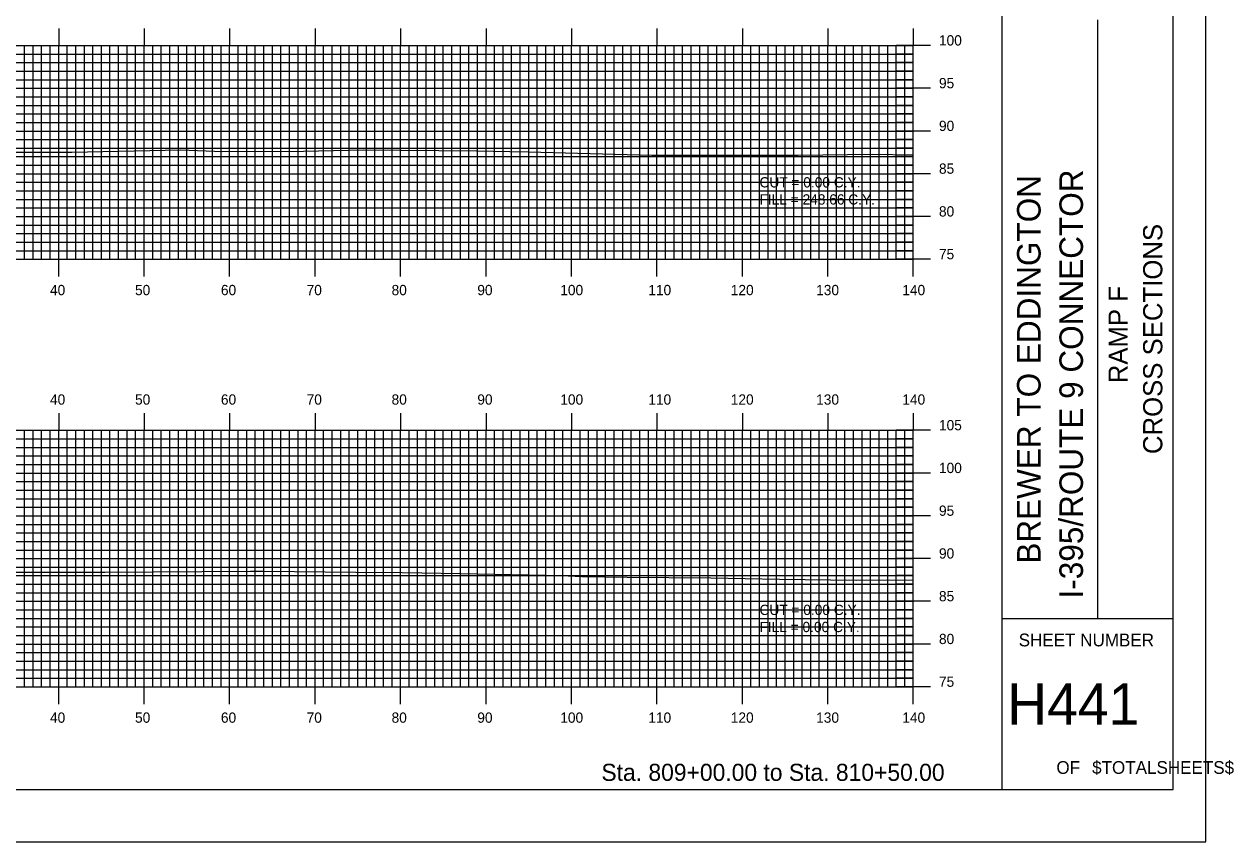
# Model space of a CAD drawing. Extents: x 1666 to 2009, y -1658 to -1438.
# Drawn here: x 1867.6 to 2009.2, y -1657.7 to -1562.1 of the extents above; entities that cross this region are included whole.
import ezdxf

# ---------------------------------------------------------------- set-up
doc = ezdxf.new("R2010")
doc.units = 0
for name, color, linetype in [('BORDER', 7, 'Continuous'), ('D_Text_Standard', 7, 'Continuous'), ('H_V ANNOTATION', 7, 'Continuous'), ('MAJOR', 7, 'Continuous'), ('MINOR', 7, 'Continuous'), ('PLOT BOUNDARY', 7, 'Continuous'), ('S_Roadway_Centerline', 7, 'Continuous')]:
    doc.layers.add(name, color=color, linetype=linetype)

msp = doc.modelspace()

# ---------------------------------------------------------------- linework, layer by layer
at = {"layer": 'BORDER'}
for p, q in [((1982.07, -1651.6), (1982.07, -1441.6)), ((1993.26, -1631.6), (1993.26, -1561.6)), ((1982.07, -1631.6), (2002.07, -1631.6))]:
    msp.add_line(p, q, dxfattribs=at)
msp.add_lwpolyline([(1682.07, -1651.6), (2002.07, -1651.6), (2002.07, -1441.6), (1682.07, -1441.6)], close=True, dxfattribs=at)
at = {"layer": 'MAJOR'}
for p, q in [((1871.67, -1562.6), (1871.67, -1564.6)), ((1881.67, -1562.6), (1881.67, -1564.6)), ((1891.67, -1562.6), (1891.67, -1564.6)), ((1901.67, -1562.6), (1901.67, -1564.6)), ((1911.67, -1562.6), (1911.67, -1564.6)), ((1921.67, -1562.6), (1921.67, -1564.6)), ((1931.67, -1562.6), (1931.67, -1564.6)), ((1941.67, -1562.6), (1941.67, -1564.6)), ((1951.67, -1562.6), (1951.67, -1564.6)), ((1961.67, -1562.6), (1961.67, -1564.6)), ((1971.67, -1562.6), (1971.67, -1564.6)), ((1691.67, -1564.6), (1971.67, -1564.6)), ((1691.67, -1564.6), (1971.67, -1564.6)), ((1871.67, -1589.6), (1871.67, -1564.6)), ((1881.67, -1589.6), (1881.67, -1564.6)), ((1891.67, -1589.6), (1891.67, -1564.6)), ((1901.67, -1589.6), (1901.67, -1564.6)), ((1911.67, -1589.6), (1911.67, -1564.6)), ((1921.67, -1589.6), (1921.67, -1564.6)), ((1931.67, -1589.6), (1931.67, -1564.6)), ((1941.67, -1589.6), (1941.67, -1564.6)), ((1951.67, -1589.6), (1951.67, -1564.6)), ((1961.67, -1589.6), (1961.67, -1564.6)), ((1973.68, -1564.6), (1969.67, -1564.6)), ((1971.67, -1589.6), (1971.67, -1564.6)), ((1971.67, -1589.6), (1971.67, -1564.6)), ((1691.67, -1569.6), (1971.67, -1569.6)), ((1973.68, -1569.6), (1969.67, -1569.6)), ((1691.67, -1574.6), (1971.67, -1574.6)), ((1973.68, -1574.6), (1969.67, -1574.6)), ((1691.67, -1579.6), (1971.67, -1579.6)), ((1973.68, -1579.6), (1969.67, -1579.6)), ((1691.67, -1584.6), (1971.67, -1584.6)), ((1973.68, -1584.6), (1969.67, -1584.6)), ((1691.67, -1589.6), (1971.67, -1589.6)), ((1691.67, -1589.6), (1971.67, -1589.6)), ((1871.67, -1591.61), (1871.67, -1589.6)), ((1881.67, -1591.61), (1881.67, -1589.6)), ((1891.67, -1591.61), (1891.67, -1589.6)), ((1901.67, -1591.61), (1901.67, -1589.6)), ((1911.67, -1591.61), (1911.67, -1589.6)), ((1921.67, -1591.61), (1921.67, -1589.6)), ((1931.67, -1591.61), (1931.67, -1589.6)), ((1941.67, -1591.61), (1941.67, -1589.6)), ((1951.67, -1591.61), (1951.67, -1589.6)), ((1961.67, -1591.61), (1961.67, -1589.6)), ((1973.68, -1589.6), (1969.67, -1589.6)), ((1971.67, -1591.61), (1971.67, -1589.6)), ((1871.67, -1607.6), (1871.67, -1609.6)), ((1881.67, -1607.6), (1881.67, -1609.6)), ((1891.67, -1607.6), (1891.67, -1609.6)), ((1901.67, -1607.6), (1901.67, -1609.6)), ((1911.67, -1607.6), (1911.67, -1609.6)), ((1921.67, -1607.6), (1921.67, -1609.6)), ((1931.67, -1607.6), (1931.67, -1609.6)), ((1941.67, -1607.6), (1941.67, -1609.6)), ((1951.67, -1607.6), (1951.67, -1609.6)), ((1961.67, -1607.6), (1961.67, -1609.6)), ((1971.67, -1607.6), (1971.67, -1609.6)), ((1691.67, -1609.6), (1971.67, -1609.6)), ((1691.67, -1609.6), (1971.67, -1609.6)), ((1871.67, -1639.6), (1871.67, -1609.6)), ((1881.67, -1639.6), (1881.67, -1609.6)), ((1891.67, -1639.6), (1891.67, -1609.6)), ((1901.67, -1639.6), (1901.67, -1609.6)), ((1911.67, -1639.6), (1911.67, -1609.6)), ((1921.67, -1639.6), (1921.67, -1609.6)), ((1931.67, -1639.6), (1931.67, -1609.6)), ((1941.67, -1639.6), (1941.67, -1609.6)), ((1951.67, -1639.6), (1951.67, -1609.6)), ((1961.67, -1639.6), (1961.67, -1609.6)), ((1973.68, -1609.6), (1969.67, -1609.6)), ((1971.67, -1639.6), (1971.67, -1609.6)), ((1971.67, -1639.6), (1971.67, -1609.6)), ((1691.67, -1614.6), (1971.67, -1614.6)), ((1973.68, -1614.6), (1969.67, -1614.6)), ((1691.67, -1619.6), (1971.67, -1619.6)), ((1973.68, -1619.6), (1969.67, -1619.6)), ((1691.67, -1624.6), (1971.67, -1624.6)), ((1973.68, -1624.6), (1969.67, -1624.6)), ((1691.67, -1629.6), (1971.67, -1629.6)), ((1973.68, -1629.6), (1969.67, -1629.6)), ((1691.67, -1634.6), (1971.67, -1634.6)), ((1973.68, -1634.6), (1969.67, -1634.6)), ((1691.67, -1639.6), (1971.67, -1639.6)), ((1691.67, -1639.6), (1971.67, -1639.6)), ((1871.67, -1641.61), (1871.67, -1639.6)), ((1881.67, -1641.61), (1881.67, -1639.6)), ((1891.67, -1641.61), (1891.67, -1639.6)), ((1901.67, -1641.61), (1901.67, -1639.6)), ((1911.67, -1641.61), (1911.67, -1639.6)), ((1921.67, -1641.61), (1921.67, -1639.6)), ((1931.67, -1641.61), (1931.67, -1639.6)), ((1941.67, -1641.61), (1941.67, -1639.6)), ((1951.67, -1641.61), (1951.67, -1639.6)), ((1961.67, -1641.61), (1961.67, -1639.6)), ((1973.68, -1639.6), (1969.67, -1639.6)), ((1971.67, -1641.61), (1971.67, -1639.6))]:
    msp.add_line(p, q, dxfattribs=at)
at = {"layer": 'MINOR'}
for p, q in [((1867.67, -1589.6), (1867.67, -1564.6)), ((1868.67, -1589.6), (1868.67, -1564.6)), ((1869.67, -1589.6), (1869.67, -1564.6)), ((1870.67, -1589.6), (1870.67, -1564.6)), ((1872.67, -1589.6), (1872.67, -1564.6)), ((1873.67, -1589.6), (1873.67, -1564.6)), ((1874.67, -1589.6), (1874.67, -1564.6)), ((1875.67, -1589.6), (1875.67, -1564.6)), ((1876.67, -1589.6), (1876.67, -1564.6)), ((1877.67, -1589.6), (1877.67, -1564.6)), ((1878.67, -1589.6), (1878.67, -1564.6)), ((1879.67, -1589.6), (1879.67, -1564.6)), ((1880.67, -1589.6), (1880.67, -1564.6)), ((1882.67, -1589.6), (1882.67, -1564.6)), ((1883.67, -1589.6), (1883.67, -1564.6)), ((1884.67, -1589.6), (1884.67, -1564.6)), ((1885.67, -1589.6), (1885.67, -1564.6)), ((1886.67, -1589.6), (1886.67, -1564.6)), ((1887.67, -1589.6), (1887.67, -1564.6)), ((1888.67, -1589.6), (1888.67, -1564.6)), ((1889.67, -1589.6), (1889.67, -1564.6)), ((1890.67, -1589.6), (1890.67, -1564.6)), ((1892.67, -1589.6), (1892.67, -1564.6)), ((1893.67, -1589.6), (1893.67, -1564.6)), ((1894.67, -1589.6), (1894.67, -1564.6)), ((1895.67, -1589.6), (1895.67, -1564.6)), ((1896.67, -1589.6), (1896.67, -1564.6)), ((1897.67, -1589.6), (1897.67, -1564.6)), ((1898.67, -1589.6), (1898.67, -1564.6)), ((1899.67, -1589.6), (1899.67, -1564.6)), ((1900.67, -1589.6), (1900.67, -1564.6)), ((1902.67, -1589.6), (1902.67, -1564.6)), ((1903.67, -1589.6), (1903.67, -1564.6)), ((1904.67, -1589.6), (1904.67, -1564.6)), ((1905.67, -1589.6), (1905.67, -1564.6)), ((1906.67, -1589.6), (1906.67, -1564.6)), ((1907.67, -1589.6), (1907.67, -1564.6)), ((1908.67, -1589.6), (1908.67, -1564.6)), ((1909.67, -1589.6), (1909.67, -1564.6)), ((1910.67, -1589.6), (1910.67, -1564.6)), ((1912.67, -1589.6), (1912.67, -1564.6)), ((1913.67, -1589.6), (1913.67, -1564.6)), ((1914.67, -1589.6), (1914.67, -1564.6)), ((1915.67, -1589.6), (1915.67, -1564.6)), ((1916.67, -1589.6), (1916.67, -1564.6)), ((1917.67, -1589.6), (1917.67, -1564.6)), ((1918.67, -1589.6), (1918.67, -1564.6)), ((1919.67, -1589.6), (1919.67, -1564.6)), ((1920.67, -1589.6), (1920.67, -1564.6)), ((1922.67, -1589.6), (1922.67, -1564.6)), ((1923.67, -1589.6), (1923.67, -1564.6)), ((1924.67, -1589.6), (1924.67, -1564.6)), ((1925.67, -1589.6), (1925.67, -1564.6)), ((1926.67, -1589.6), (1926.67, -1564.6)), ((1927.67, -1589.6), (1927.67, -1564.6)), ((1928.67, -1589.6), (1928.67, -1564.6)), ((1929.67, -1589.6), (1929.67, -1564.6)), ((1930.67, -1589.6), (1930.67, -1564.6)), ((1932.67, -1589.6), (1932.67, -1564.6)), ((1933.67, -1589.6), (1933.67, -1564.6)), ((1934.67, -1589.6), (1934.67, -1564.6)), ((1935.67, -1589.6), (1935.67, -1564.6)), ((1936.67, -1589.6), (1936.67, -1564.6)), ((1937.67, -1589.6), (1937.67, -1564.6)), ((1938.67, -1589.6), (1938.67, -1564.6)), ((1939.67, -1589.6), (1939.67, -1564.6)), ((1940.67, -1589.6), (1940.67, -1564.6)), ((1942.67, -1589.6), (1942.67, -1564.6)), ((1943.67, -1589.6), (1943.67, -1564.6)), ((1944.67, -1589.6), (1944.67, -1564.6)), ((1945.67, -1589.6), (1945.67, -1564.6)), ((1946.67, -1589.6), (1946.67, -1564.6)), ((1947.67, -1589.6), (1947.67, -1564.6)), ((1948.67, -1589.6), (1948.67, -1564.6)), ((1949.67, -1589.6), (1949.67, -1564.6)), ((1950.67, -1589.6), (1950.67, -1564.6)), ((1952.67, -1589.6), (1952.67, -1564.6)), ((1953.67, -1589.6), (1953.67, -1564.6)), ((1954.67, -1589.6), (1954.67, -1564.6)), ((1955.67, -1589.6), (1955.67, -1564.6)), ((1956.67, -1589.6), (1956.67, -1564.6)), ((1957.67, -1589.6), (1957.67, -1564.6)), ((1958.67, -1589.6), (1958.67, -1564.6)), ((1959.67, -1589.6), (1959.67, -1564.6)), ((1960.67, -1589.6), (1960.67, -1564.6)), ((1962.67, -1589.6), (1962.67, -1564.6)), ((1963.67, -1589.6), (1963.67, -1564.6)), ((1964.67, -1589.6), (1964.67, -1564.6)), ((1965.67, -1589.6), (1965.67, -1564.6)), ((1966.67, -1589.6), (1966.67, -1564.6)), ((1967.67, -1589.6), (1967.67, -1564.6)), ((1968.67, -1589.6), (1968.67, -1564.6)), ((1969.67, -1589.6), (1969.67, -1564.6)), ((1970.67, -1589.6), (1970.67, -1564.6)), ((1691.67, -1565.6), (1971.67, -1565.6)), ((1691.67, -1566.6), (1971.67, -1566.6)), ((1971.67, -1565.6), (1969.67, -1565.6)), ((1971.67, -1566.6), (1969.67, -1566.6)), ((1691.67, -1567.6), (1971.67, -1567.6)), ((1971.67, -1567.6), (1969.67, -1567.6)), ((1691.67, -1568.6), (1971.67, -1568.6)), ((1971.67, -1568.6), (1969.67, -1568.6)), ((1691.67, -1570.6), (1971.67, -1570.6)), ((1971.67, -1570.6), (1969.67, -1570.6)), ((1691.67, -1571.6), (1971.67, -1571.6)), ((1971.67, -1571.6), (1969.67, -1571.6)), ((1691.67, -1572.6), (1971.67, -1572.6)), ((1691.67, -1573.6), (1971.67, -1573.6)), ((1971.67, -1572.6), (1969.67, -1572.6)), ((1971.67, -1573.6), (1969.67, -1573.6)), ((1691.67, -1575.6), (1971.67, -1575.6)), ((1691.67, -1576.6), (1971.67, -1576.6)), ((1971.67, -1575.6), (1969.67, -1575.6)), ((1971.67, -1576.6), (1969.67, -1576.6)), ((1691.67, -1577.6), (1971.67, -1577.6)), ((1971.67, -1577.6), (1969.67, -1577.6)), ((1691.67, -1578.6), (1971.67, -1578.6)), ((1971.67, -1578.6), (1969.67, -1578.6)), ((1691.67, -1580.6), (1971.67, -1580.6)), ((1971.67, -1580.6), (1969.67, -1580.6)), ((1691.67, -1581.6), (1971.67, -1581.6)), ((1971.67, -1581.6), (1969.67, -1581.6)), ((1691.67, -1582.6), (1971.67, -1582.6)), ((1691.67, -1583.6), (1971.67, -1583.6)), ((1971.67, -1582.6), (1969.67, -1582.6)), ((1971.67, -1583.6), (1969.67, -1583.6)), ((1691.67, -1585.6), (1971.67, -1585.6)), ((1691.67, -1586.6), (1971.67, -1586.6)), ((1971.67, -1585.6), (1969.67, -1585.6)), ((1971.67, -1586.6), (1969.67, -1586.6)), ((1691.67, -1587.6), (1971.67, -1587.6)), ((1971.67, -1587.6), (1969.67, -1587.6)), ((1691.67, -1588.6), (1971.67, -1588.6)), ((1971.67, -1588.6), (1969.67, -1588.6)), ((1691.67, -1610.6), (1971.67, -1610.6)), ((1867.67, -1639.6), (1867.67, -1609.6)), ((1868.67, -1639.6), (1868.67, -1609.6)), ((1869.67, -1639.6), (1869.67, -1609.6)), ((1870.67, -1639.6), (1870.67, -1609.6)), ((1872.67, -1639.6), (1872.67, -1609.6)), ((1873.67, -1639.6), (1873.67, -1609.6)), ((1874.67, -1639.6), (1874.67, -1609.6)), ((1875.67, -1639.6), (1875.67, -1609.6)), ((1876.67, -1639.6), (1876.67, -1609.6)), ((1877.67, -1639.6), (1877.67, -1609.6)), ((1878.67, -1639.6), (1878.67, -1609.6)), ((1879.67, -1639.6), (1879.67, -1609.6)), ((1880.67, -1639.6), (1880.67, -1609.6)), ((1882.67, -1639.6), (1882.67, -1609.6)), ((1883.67, -1639.6), (1883.67, -1609.6)), ((1884.67, -1639.6), (1884.67, -1609.6)), ((1885.67, -1639.6), (1885.67, -1609.6)), ((1886.67, -1639.6), (1886.67, -1609.6)), ((1887.67, -1639.6), (1887.67, -1609.6)), ((1888.67, -1639.6), (1888.67, -1609.6)), ((1889.67, -1639.6), (1889.67, -1609.6)), ((1890.67, -1639.6), (1890.67, -1609.6)), ((1892.67, -1639.6), (1892.67, -1609.6)), ((1893.67, -1639.6), (1893.67, -1609.6)), ((1894.67, -1639.6), (1894.67, -1609.6)), ((1895.67, -1639.6), (1895.67, -1609.6)), ((1896.67, -1639.6), (1896.67, -1609.6)), ((1897.67, -1639.6), (1897.67, -1609.6)), ((1898.67, -1639.6), (1898.67, -1609.6)), ((1899.67, -1639.6), (1899.67, -1609.6)), ((1900.67, -1639.6), (1900.67, -1609.6)), ((1902.67, -1639.6), (1902.67, -1609.6)), ((1903.67, -1639.6), (1903.67, -1609.6)), ((1904.67, -1639.6), (1904.67, -1609.6)), ((1905.67, -1639.6), (1905.67, -1609.6)), ((1906.67, -1639.6), (1906.67, -1609.6)), ((1907.67, -1639.6), (1907.67, -1609.6)), ((1908.67, -1639.6), (1908.67, -1609.6)), ((1909.67, -1639.6), (1909.67, -1609.6)), ((1910.67, -1639.6), (1910.67, -1609.6)), ((1912.67, -1639.6), (1912.67, -1609.6)), ((1913.67, -1639.6), (1913.67, -1609.6)), ((1914.67, -1639.6), (1914.67, -1609.6)), ((1915.67, -1639.6), (1915.67, -1609.6)), ((1916.67, -1639.6), (1916.67, -1609.6)), ((1917.67, -1639.6), (1917.67, -1609.6)), ((1918.67, -1639.6), (1918.67, -1609.6)), ((1919.67, -1639.6), (1919.67, -1609.6)), ((1920.67, -1639.6), (1920.67, -1609.6)), ((1922.67, -1639.6), (1922.67, -1609.6)), ((1923.67, -1639.6), (1923.67, -1609.6)), ((1924.67, -1639.6), (1924.67, -1609.6)), ((1925.67, -1639.6), (1925.67, -1609.6)), ((1926.67, -1639.6), (1926.67, -1609.6)), ((1927.67, -1639.6), (1927.67, -1609.6)), ((1928.67, -1639.6), (1928.67, -1609.6)), ((1929.67, -1639.6), (1929.67, -1609.6)), ((1930.67, -1639.6), (1930.67, -1609.6)), ((1932.67, -1639.6), (1932.67, -1609.6)), ((1933.67, -1639.6), (1933.67, -1609.6)), ((1934.67, -1639.6), (1934.67, -1609.6)), ((1935.67, -1639.6), (1935.67, -1609.6)), ((1936.67, -1639.6), (1936.67, -1609.6)), ((1937.67, -1639.6), (1937.67, -1609.6)), ((1938.67, -1639.6), (1938.67, -1609.6)), ((1939.67, -1639.6), (1939.67, -1609.6)), ((1940.67, -1639.6), (1940.67, -1609.6)), ((1942.67, -1639.6), (1942.67, -1609.6)), ((1943.67, -1639.6), (1943.67, -1609.6)), ((1944.67, -1639.6), (1944.67, -1609.6)), ((1945.67, -1639.6), (1945.67, -1609.6)), ((1946.67, -1639.6), (1946.67, -1609.6)), ((1947.67, -1639.6), (1947.67, -1609.6)), ((1948.67, -1639.6), (1948.67, -1609.6)), ((1949.67, -1639.6), (1949.67, -1609.6)), ((1950.67, -1639.6), (1950.67, -1609.6)), ((1952.67, -1639.6), (1952.67, -1609.6)), ((1953.67, -1639.6), (1953.67, -1609.6)), ((1954.67, -1639.6), (1954.67, -1609.6)), ((1955.67, -1639.6), (1955.67, -1609.6)), ((1956.67, -1639.6), (1956.67, -1609.6)), ((1957.67, -1639.6), (1957.67, -1609.6)), ((1958.67, -1639.6), (1958.67, -1609.6)), ((1959.67, -1639.6), (1959.67, -1609.6)), ((1960.67, -1639.6), (1960.67, -1609.6)), ((1962.67, -1639.6), (1962.67, -1609.6)), ((1963.67, -1639.6), (1963.67, -1609.6)), ((1964.67, -1639.6), (1964.67, -1609.6)), ((1965.67, -1639.6), (1965.67, -1609.6)), ((1966.67, -1639.6), (1966.67, -1609.6)), ((1967.67, -1639.6), (1967.67, -1609.6)), ((1968.67, -1639.6), (1968.67, -1609.6)), ((1969.67, -1639.6), (1969.67, -1609.6)), ((1971.67, -1610.6), (1969.67, -1610.6)), ((1970.67, -1639.6), (1970.67, -1609.6)), ((1691.67, -1611.6), (1971.67, -1611.6)), ((1971.67, -1611.6), (1969.67, -1611.6)), ((1691.67, -1612.6), (1971.67, -1612.6)), ((1971.67, -1612.6), (1969.67, -1612.6)), ((1691.67, -1613.6), (1971.67, -1613.6)), ((1971.67, -1613.6), (1969.67, -1613.6)), ((1691.67, -1615.6), (1971.67, -1615.6)), ((1971.67, -1615.6), (1969.67, -1615.6)), ((1691.67, -1616.6), (1971.67, -1616.6)), ((1691.67, -1617.6), (1971.67, -1617.6)), ((1971.67, -1616.6), (1969.67, -1616.6)), ((1971.67, -1617.6), (1969.67, -1617.6)), ((1691.67, -1618.6), (1971.67, -1618.6)), ((1971.67, -1618.6), (1969.67, -1618.6)), ((1691.67, -1620.6), (1971.67, -1620.6)), ((1971.67, -1620.6), (1969.67, -1620.6)), ((1691.67, -1621.6), (1971.67, -1621.6)), ((1971.67, -1621.6), (1969.67, -1621.6)), ((1691.67, -1622.6), (1971.67, -1622.6)), ((1971.67, -1622.6), (1969.67, -1622.6)), ((1691.67, -1623.6), (1971.67, -1623.6)), ((1971.67, -1623.6), (1969.67, -1623.6)), ((1691.67, -1625.6), (1971.67, -1625.6)), ((1971.67, -1625.6), (1969.67, -1625.6)), ((1691.67, -1626.6), (1971.67, -1626.6)), ((1691.67, -1627.6), (1971.67, -1627.6)), ((1971.67, -1626.6), (1969.67, -1626.6)), ((1971.67, -1627.6), (1969.67, -1627.6)), ((1691.67, -1628.6), (1971.67, -1628.6)), ((1971.67, -1628.6), (1969.67, -1628.6)), ((1691.67, -1630.6), (1971.67, -1630.6)), ((1691.67, -1631.6), (1971.67, -1631.6)), ((1971.67, -1630.6), (1969.67, -1630.6)), ((1971.67, -1631.6), (1969.67, -1631.6)), ((1691.67, -1632.6), (1971.67, -1632.6)), ((1971.67, -1632.6), (1969.67, -1632.6)), ((1691.67, -1633.6), (1971.67, -1633.6)), ((1971.67, -1633.6), (1969.67, -1633.6)), ((1691.67, -1635.6), (1971.67, -1635.6)), ((1971.67, -1635.6), (1969.67, -1635.6)), ((1691.67, -1636.6), (1971.67, -1636.6)), ((1971.67, -1636.6), (1969.67, -1636.6)), ((1691.67, -1637.6), (1971.67, -1637.6)), ((1691.67, -1638.6), (1971.67, -1638.6)), ((1971.67, -1637.6), (1969.67, -1637.6)), ((1971.67, -1638.6), (1969.67, -1638.6))]:
    msp.add_line(p, q, dxfattribs=at)
at = {"layer": 'PLOT BOUNDARY'}
msp.add_lwpolyline([(1665.89, -1657.72), (2005.89, -1657.72), (2005.89, -1437.72), (1665.89, -1437.72)], close=True, dxfattribs=at)
at = {"layer": 'S_Roadway_Centerline'}
for points in [[(1865.74, -1577.06), (1871.37, -1577.09), (1873.2, -1577.06), (1885.96, -1576.81), (1890.88, -1577.01), (1900.32, -1576.97), (1907.32, -1576.82), (1920.55, -1576.91), (1924.47, -1577.01), (1926.64, -1577.05), (1941.08, -1577.41), (1941.7, -1577.42), (1941.81, -1577.42), (1941.98, -1577.43), (1958.18, -1577.41), (1966.84, -1577.3), (1971.67, -1577.38)], [(1864.85, -1626.2), (1877.05, -1626.2), (1894.1, -1626.09), (1895.66, -1626.09), (1906.45, -1626.18), (1911.86, -1626.23), (1918.71, -1626.34), (1930.51, -1626.59), (1932.89, -1626.68), (1938.17, -1626.76), (1947.99, -1626.87), (1956, -1627.01), (1964.98, -1627.14), (1971.67, -1627.08)]]:
    msp.add_lwpolyline(points, dxfattribs=at)

# ---------------------------------------------------------------- texts
at = {"layer": 'BORDER'}
for s, height, p in [('I-395/ROUTE 9 CONNECTOR', 2.7557, (1991.52, -1629.27)), ('BREWER TO EDDINGTON', 2.7557, (1986.56, -1625.2)), ('CROSS SECTIONS', 2.25, (2000.81, -1612.38)), ('RAMP F', 2.25, (1996.76, -1604.1))]:
    msp.add_text(s, height=height, rotation=90, dxfattribs=at).set_placement(p)
for s, height, p in [('SHEET NUMBER', 1.4905, (1984, -1634.87)), ('H441', 4.839, (1982.65, -1644.04)), ('OF', 1.491, (1988.41, -1649.78)), ('$TOTALSHEETS$', 1.4905, (1992.59, -1649.78))]:
    msp.add_text(s, height=height, dxfattribs=at).set_placement(p)
at = {"layer": 'D_Text_Standard'}
for s, p in [('CUT = 0.00 C.Y.', (1953.67, -1581.2)), ('FILL = 248.66 C.Y.', (1953.67, -1583.2)), ('CUT = 0.00 C.Y.', (1953.67, -1631.2)), ('FILL = 0.00 C.Y.', (1953.67, -1633.2))]:
    msp.add_text(s, height=1.2, dxfattribs=at).set_placement(p)
at = {"layer": 'H_V ANNOTATION'}
for s, height, p in [('100', 1.2, (1974.67, -1564.6)), ('95', 1.2, (1974.67, -1569.6)), ('90', 1.2, (1974.67, -1574.6)), ('85', 1.2, (1974.67, -1579.6)), ('80', 1.2, (1974.67, -1584.6)), ('75', 1.2, (1974.67, -1589.6)), ('40', 1.2, (1870.65, -1593.8)), ('50', 1.2, (1880.6, -1593.8)), ('60', 1.2, (1890.65, -1593.8)), ('70', 1.2, (1900.68, -1593.8)), ('80', 1.2, (1910.62, -1593.8)), ('90', 1.2, (1920.65, -1593.8)), ('100', 1.2, (1930.36, -1593.8)), ('110', 1.2, (1940.66, -1593.8)), ('120', 1.2, (1950.31, -1593.8)), ('130', 1.2, (1960.3, -1593.8)), ('140', 1.2, (1970.38, -1593.8)), ('40', 1.2, (1870.65, -1606.6)), ('50', 1.2, (1880.6, -1606.6)), ('60', 1.2, (1890.65, -1606.6)), ('70', 1.2, (1900.68, -1606.6)), ('80', 1.2, (1910.62, -1606.6)), ('90', 1.2, (1920.65, -1606.6)), ('100', 1.2, (1930.36, -1606.6)), ('110', 1.2, (1940.66, -1606.6)), ('120', 1.2, (1950.31, -1606.6)), ('130', 1.2, (1960.3, -1606.6)), ('140', 1.2, (1970.38, -1606.6)), ('105', 1.2, (1974.67, -1609.6)), ('100', 1.2, (1974.67, -1614.6)), ('95', 1.2, (1974.67, -1619.6)), ('90', 1.2, (1974.67, -1624.6)), ('85', 1.2, (1974.67, -1629.6)), ('80', 1.2, (1974.67, -1634.6)), ('75', 1.2, (1974.67, -1639.6)), ('40', 1.2, (1870.65, -1643.8)), ('50', 1.2, (1880.6, -1643.8)), ('60', 1.2, (1890.65, -1643.8)), ('70', 1.2, (1900.68, -1643.8)), ('80', 1.2, (1910.62, -1643.8)), ('90', 1.2, (1920.65, -1643.8)), ('100', 1.2, (1930.36, -1643.8)), ('110', 1.2, (1940.66, -1643.8)), ('120', 1.2, (1950.31, -1643.8)), ('130', 1.2, (1960.3, -1643.8)), ('140', 1.2, (1970.38, -1643.8)), ('Sta. 809+00.00 to Sta. 810+50.00', 2.0004, (1935.17, -1650.6))]:
    msp.add_text(s, height=height, dxfattribs=at).set_placement(p)

doc.saveas('drawing.dxf')
